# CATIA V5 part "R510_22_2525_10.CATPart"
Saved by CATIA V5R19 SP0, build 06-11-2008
Material "Steel": density 7860 kg/m3, Young's modulus 2e+11 Pa, Poisson ratio 0.266, thermal expansion 1.17e-05 1/K
Bounding box of the stored display mesh (mm): x -12.5 to 12.497, y -12.358 to 12.439, z 0 to 96
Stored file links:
  G:\Podręcznik\CD\Narzędzia\Arkusz Excel\Modele narzędzi\R510.22-2525-10.CATPart
  C:\Program Files\Dassault Systemes\B19\intel_a\startup\materials\Catalog.CATMaterial
  F:\OSTATNIE\DesignTable2.xls
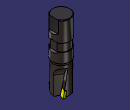
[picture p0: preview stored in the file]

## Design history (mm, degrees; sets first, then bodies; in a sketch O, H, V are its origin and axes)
Parameters
  CuttingType = "CUTTER"
  d = 25 mm {design table}
  D = 25 mm {design table}
  L = 96 mm {design table}
  l = 56 mm {design table}
  alfa = 11 deg {design table}
  gammap = 9 deg {design table}
  S = 3.18 mm {design table}
  epsilon = 85 deg {design table}
  lp = 10 mm {design table}
  x = 0.1131 mm {design table}
  gammaf = -12 deg {design table}
  z = 3 {design table}
  teta = 120 deg {design table}
  `lp'` = 9.8769 mm {design table}
  `lp''` = 5.8466 mm {design table}
Body1 "BODY" (main body), material "Steel"
  Sketch1 "sketch" on yz-plane, origin (0, 0, 0), H (0, 1, 0), V (0, 0, 1)
    line L1 (0, 1.6479) -> (11.5, 0.2358)
    line L2 (11.5, 0.2358) -> (11.5, 40)
    point P3 (11.5, 40)
    line L3 (11.5, 40) -> (11.5, 40)
    point P4 (12.5, 40)
    line L4 (12.5, 43.2077) -> (12.5, 56.8)
    point P5 (12.5, 56.8)
    line L5 (12.5, 56.8) -> (11.5, 56.8)
    line L6 (11.5, 56.8) -> (11.5, 68)
    line L7 (11.5, 68) -> (12.5, 68)
    point P8 (12.5, 68)
    line L8 (12.5, 68) -> (12.5, 95.2929)
    line L9 (12.5, 95.2929) -> (11.7929, 96)
    line L10 (11.7929, 96) -> (0, 96)
    point P11 (0, 96)
    line L11 (0, 96) -> (0, 1.6479)
    construction line L12 (0, -29.1199) -> (0, 199.3445)
    point P12 (0, -29.1199)
    construction line L13 (0, 0.1131) -> (12.5, 0.1131)
    point P14 (0, 0.1131)
    point P15 (12.5, 0.1131)
    construction line L14 (0, 1.6479) -> (12.5, 0.1131)
    axis line L15 (12.5, 0.1131) -> (12.5, -5.5625)
    line L16 (11.5, 40) -> (12.5, 43.2077)
    point P17 (11.5, 40)
    length L6 = 11.2 {= 0.2*l}
    distance P3 H = 40 {= L-l}
    length L9 = 1
    angle L8 L9 = 45
    distance L6 L8 = 1
    distance L8 L11 = 12.5 {= d/2}
    length L13 = 12.5 {= D/2}
    distance H L13 = 0.1131 {= x}
    distance L10 L7 = 28 {= 0.5*l}
    distance P15 L2 = 1
    distance P4 P5 = 16.8 {= 0.3*l}
    length L16 = 3.36 {= 0.2*(0.3*l)}
    angle L1 L2 = 83
    vertical: L2 V, L4 V, L6 V, L8 V, L11 V, L12 V, L15 V
    horizontal: L3 H, L5 H, L7 H, L10 H, L13 H
    coincidence: P8 L4, P11 V, P12 V, L1 L14, P14 L12, L3 P4, L4 P4, P3 P17
  Shaft1: profile Sketch1, axis Z axis, angle 360
  Fillet1: radius 1.25 {= 0.1*D/2}, on edge [face of Shaft1 from Sketch1.L1 | face of Shaft1 from Sketch1.L2]
  Sketch2 on zx-plane, origin (0, 0, 0), H (-1, 0, 0), V (0, 0, 1)
    line L1 (-10.5, 96) -> (-10.5, 79.2)
    line L2 (-10.5, 79.2) -> (-12.5, 77.2)
    line L3 (-12.5, 77.2) -> (-12.5, 70)
    line L4 (-12.5, 70) -> (-10.5, 68)
    point P5 (-10.5, 68)
    line L5 (-10.5, 68) -> (-10.5, 56.8)
    line L6 (-10.5, 56.8) -> (-12.5, 54.8)
    point P7 (-12.5, 54.8)
    line L7 (-12.5, 54.8) -> (-12.5, 54.8)
    line L8 (-12.5, 54.8) -> (-15.5, 54.8)
    line L9 (-15.5, 54.8) -> (-15.5, 96)
    line L10 (-15.5, 96) -> (-10.5, 96)
    reference projected line E1 through (0, 0) direction (0, 1) from axis of face of Shaft1 from Sketch1.L8
    reference projected line E2 (-9.2929, 96) -> (9.2929, 96) from edge [face of Shaft1 from Sketch1.L9 | face of Shaft1 from Sketch1.L10]
    distance L3 E1 = 12.5 {= d/2}
    distance L1 L3 = 2
    angle L2 L3 = 45
    angle L4 L3 = 45
    length L5 = 11.2 {= l*0.2}
    length L1 = 16.8 {= 0.3*l}
    distance P5 L10 = 28 {= 0.5*l}
    distance L9 L1 = 5
    distance L7 L5 = 2
    angle L5 L6 = 45
    vertical: L1 V, L3 V, L5 V, L7 V, L9 V
    horizontal: L8 H, L10 H
    coincidence: L10 E2, L1 L5, P7 L8
  Pocket1: profile Sketch2, direction (0, -1, 0), length 8, mirrored extent
  Plane1: type Angle, Angle 150, Direction Z axis, RefPlane yz-plane
  Plane2: type Offset, Offset 1, RefPlane Plane1, reversed
  Sketch3 "gammap_os_obrotu" on Plane2, origin (0.866, -0.5, 0), H (-0.5, -0.866, 0), V (0, 0, 1)
    line L1 (1.3076, 0) -> (-0.9434, 0)
    reference intersected line E1 through (0, 0) direction (-1, 0) from xy-plane
    horizontal: L1 H
    coincidence: E1 L1
  Plane3 "gammap": type Angle, Angle -9 {= -gammap}, Direction Sketch3, RefPlane Plane2
  Plane4: type Offset, Offset 0.5, RefPlane Plane3, reversed
  Sketch4 on Plane4, origin (1.2725, -0.7347, 0.2327), H (-0.5, -0.866, 0), V (-0.1355, 0.0782, 0.9877)
    line L1 (-12.5, -2.3223) -> (-12.5, 6.2448)
    distance V L1 = 12.5 {= D/2}
  Plane5 "gammaf": type Angle, Angle 12 {= -gammaf}, Direction Sketch4, RefPlane Plane4
  Plane6: type Offset, Offset 0.5, RefPlane Plane5
  Plane7: type Angle, Angle 90, Direction Sketch4, RefPlane Plane5
  Sketch5 on Plane7, origin (3.6327, 11.3423, -0.4372), H (0.9503, -0.3114, 0), V (0.0101, 0.0309, 0.9995)
    point P1 (4.1222, 0.4375)
    line L1 (4.1222, 0.4375) -> (0.8851, 0.5615)
    line L2 (0.8851, 0.5615) -> (-0.4566, 9.2219)
    line L3 (-0.4566, 9.2219) -> (2.5913, 10.3196)
    line L4 (2.5913, 10.3196) -> (4.1222, 0.4375)
    reference projected line E1 (4.4403, -1.6156) -> (3.1287, 6.8505) from Sketch4
    construction line L5 (2.5913, 10.3196) -> (-2.3113, 9.5601)
    axis line L6 (4.1222, 0.4375) -> (0.4321, -0.1342)
    reference intersected line E2 through (-0.0001, 0.4375) direction (-1, 0) from xy-plane
    distance L2 L4 = 3.18 {= S}
    length L4 = 10 {= lp}
    angle L5 L3 = 11 {= alfa}
    angle L6 L1 = 11 {= alfa}
    coincidence: L4 E1, P1 E2
    perpendicularity: L5 L2
    parallelism: L6 L5
  Plane8: type Offset, Offset 12.5 {= D/2}, RefPlane Plane1, reversed
  Sketch6 on Plane8, origin (10.8253, -6.25, 0), H (-0.5, -0.866, 0), V (0, 0, 1)
    line L1 (-6.0247, -3) -> (-6.0247, 26.3474)
    arc A1 centre (-18.0247, 26.3474) radius 12 from (-6.0247, 26.3474) to (-12.5, 37) ccw
    point P4 (-12.5, 37)
    line L2 (-12.5, 37) -> (-12.5, -3)
    point P5 (-12.5, -3)
    line L3 (-12.5, -3) -> (-6.0247, -3)
    axis line L4 (-12.5, -3) -> (-6.0247, -2.4335)
    point P6 (-12.5, -3)
    point P7 (-6.0247, -2.4335)
    reference projected line E1 (-9, 40) -> (9, 40) from edge [face of Shaft1 from Sketch1.L2 | face of Shaft1 from Sketch1.L16]
    distance L2 V = 12.5 {= D/2}
    angle L4 L2 = 85 {= epsilon}
    distance E1 P4 = 3
    radius A1 = 12
    distance H L3 = 3
    length L4 = 6.5 {= 0.65*lp}
    vertical: L1 V, L2 V
    horizontal: L3 H
    tangency: L1 A1
    coincidence: P6 P5, P7 L1
  Pocket2: profile Sketch6, direction (-0.866, 0.5, 0), up to Plane6
  CircPattern1: of Pocket2, instances 3 {= z}, angular step 120 {= teta}, axis from Z axis
  Sketch7 on Plane5, origin (3.8128, -1.2056, 0.6689), H (-0.3066, -0.9518, 0), V (-0.1456, 0.0469, 0.9882)
    line L1 (-12.211, 9.3177) -> (-6.2543, 10.037)
    point P1 (-12.211, 9.3177)
    reference projected point E1 (-12.211, 9.3177) from vertex [element of Sketch5 | element of Sketch5]
    reference projected line E2 (-11.8719, -0.9795) -> (-12.201, 9.0151) from Sketch5.L4
    length L1 = 6 {= 0.6*lp}
    angle E2 L1 = 85 {= epsilon}
    coincidence: P1 E1
  Slot1: profile Sketch5, centre curve Sketch7
  CircPattern2: of Slot1, instances 3 {= z}, angular step 120 {= teta}, axis from Z axis
Body2 "INSERTS"
  Sketch8 "CUT" on yz-plane, origin (0, 0, 0), H (0, 1, 0), V (0, 0, 1)
    line L1 (6.6757, 0.5096) -> (12.5, 0)
    point P2 (12.5, 0)
    line L2 (12.5, 0) -> (12.5, 9.8769)
    line L3 (12.5, 9.8769) -> (6.6757, 10.3864)
    line L4 (6.6757, 10.3864) -> (6.6757, 0.5096)
    angle L3 L4 = 85
    length L2 = 9.8769 {= `lp'`}
    length L1 = 5.8466 {= `lp''`}
    distance L2 V = 12.5 {= D/2}
    vertical: L2 V, L4 V
    parallelism: L3 L1
    coincidence: P2 H
  Sketch9 "NOCUT" on yz-plane, origin (0, 0, 0), H (0, 1, 0), V (0, 0, 1)
    axis line L1 (12.5, 0) -> (0, 1.0936)
    point P1 (0, 1.0936)
    point P2 (12.5, 0)
    reference projected line E1 (4.0418, 0.74) -> (10.019, 0.2171) from Sketch8.L1
    reference projected point E2 (12.5, 0) from vertex [element of Sketch8 | element of Sketch8]
    line L2 (0, 1.0936) -> (6.6757, 0.5096)
    point P3 (6.6757, 0.5096)
    line L3 (6.6757, 0.5096) -> (6.6757, 10.3864)
    line L4 (6.6757, 10.3864) -> (11.5, 9.9644)
    line L5 (11.5, 9.9644) -> (11.5, 40)
    line L6 (11.5, 40) -> (12.5, 40)
    line L7 (12.5, 40) -> (12.5, 56.8)
    line L8 (12.5, 56.8) -> (11.5, 56.8)
    line L9 (11.5, 56.8) -> (11.5, 68)
    line L10 (11.5, 68) -> (12.5, 68)
    point P11 (12.5, 68)
    line L11 (12.5, 68) -> (12.5, 95.2929)
    point P12 (12.5, 96)
    line L12 (11.7929, 96) -> (0, 96)
    point P13 (0, 96)
    line L13 (0, 96) -> (0, 1.0936)
    line L14 (12.5, 95.2929) -> (11.7929, 96)
    length L9 = 11.2 {= 0.2*l}
    length L7 = 16.8 {= 0.3*l}
    distance L6 H = 40 {= L-l}
    distance L11 L13 = 12.5 {= d/2}
    distance L9 L11 = 1
    distance P3 P2 = 5.8466 {= `lp''`}
    distance L9 L7 = 1
    distance L5 P2 = 1
    length L3 = 9.8769 {= `lp'`}
    angle L10 L9 = 90
    distance P11 P12 = 28 {= 0.5*l}
    angle L11 L14 = 45
    length L14 = 1
    coincidence: P1 V, L1 E1, P2 E2, P13 V, L11 P12, L12 P12
    parallelism: L2 L1, L4 L1
    vertical: L3 V, L5 V, L7 V, L9 V, L11 V, L13 V
    horizontal: L6 H, L8 H, L12 H
  Sketch10 on Plane7, origin (3.6327, 11.3423, -0.4372), H (0.9503, -0.3114, 0), V (0.0101, 0.0309, 0.9995)
    point P1 (4.1222, 0.4375)
    line L1 (4.1222, 0.4375) -> (0.8851, 0.5615)
    line L2 (0.8851, 0.5615) -> (-0.4566, 9.2219)
    line L3 (-0.4566, 9.2219) -> (2.5913, 10.3196)
    line L4 (2.5913, 10.3196) -> (4.1222, 0.4375)
    reference intersected line E1 through (4.0848, 0.6794) direction (0.1531, -0.9882) from Plane5
    reference intersected line E2 through (-0.0001, 0.4375) direction (-1, 0) from xy-plane
    construction line L5 (2.5913, 10.3196) -> (-8.2595, 8.6386)
    axis line L6 (4.1222, 0.4375) -> (-2.4885, -0.5867)
    distance L2 L4 = 3.18 {= S}
    length L4 = 10 {= lp}
    angle L3 L5 = 11 {= alfa}
    angle L6 L1 = 11 {= alfa}
    coincidence: L4 E1, E2 P1
    perpendicularity: L5 L2
    parallelism: L6 L5
  Sketch11 on Plane5, origin (3.8128, -1.2056, 0.6689), H (-0.3066, -0.9518, 0), V (-0.1456, 0.0469, 0.9882)
    line L1 (-12.211, 9.3177) -> (-6.2543, 10.037)
    point P1 (-12.211, 9.3177)
    reference projected point E1 (-12.211, 9.3177) from vertex [element of Sketch10 | element of Sketch10]
    reference projected line E2 (-11.8822, -0.6678) -> (-12.2113, 9.3268) from Sketch10.L4
    angle L1 E2 = 85 {= epsilon}
    length L1 = 6 {= 0.6*lp}
    coincidence: P1 E1
  Rib1: profile Sketch10, centre curve Sketch11
  CircPattern3: of the body so far, instances 3 {= z}, angular step 120 {= teta}, axis from Z axis
  Sketch12 on face of Rib1, origin (0.1021, 0.164, 1.5481), H (0.8083, -0.5887, 0), V (-0.5842, -0.8021, 0.1239)
    point P1 (0.1906, -12.4928)
    line L1 (0.1906, -12.4928) -> (-2.7056, -10.8886)
    line L2 (-2.7056, -10.8886) -> (-2.8906, -11.4927)
    point P3 (-2.8906, -11.4927)
    line L3 (-2.8906, -11.4927) -> (0.1906, -12.4928)
    reference projected point E1 (0.1906, -12.4928) from vertex [face of Rib1 | face of Rib1 | face of Rib1]
    reference projected line E2 (-3.4161, -11.3221) -> (-0.3349, -12.3222) from edge [face of Rib1 | face of Rib1]
    reference projected point E3 (-2.8906, -11.4927) from vertex [face of Rib1 | face of Rib1 | face of Rib1]
    reference projected line E4 (-2.1798, -9.1719) -> (-0.4227, -3.435) from edge [face of Rib1 | face of Rib1]
    angle L1 L3 = 11
    coincidence: E1 P1, L3 E2, P3 E3, L2 E4
  Pocket3: profile Sketch12, direction along edge [face of Rib1 | face of Rib1], length 10 {= lp}
  CircPattern4: of Pocket3, instances 3 {= z}, angular step 120 {= teta}, axis from Z axis
Relations
  design table, configuration 3, drives d, D, L, l, alfa, gammap, S, epsilon, lp, x, gammaf, z, teta, `lp'`, `lp''`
